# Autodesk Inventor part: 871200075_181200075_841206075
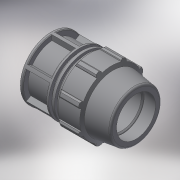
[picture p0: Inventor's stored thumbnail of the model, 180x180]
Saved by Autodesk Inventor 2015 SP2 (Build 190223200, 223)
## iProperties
Created: 2017-02
Part Number: 871200075_181200075_841206075
Material: Generic
Description: PLASSON END PLUG 75
Document SubType Name: Modeling
Designer: KIM
Mass: 947.017 g
Surface Area: 1382.98 cm^2
Volume: 947.017 cm^3
Density: 1 g/cm^3
Appearance: Default
Author: Кирилл
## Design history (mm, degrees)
derived "87120.ipt"
feature "Solid1::87120.ipt"
tag "TaggingFeature1"
body "Solid1"
other parameters: "d2" = 75, "d4" = 25.28571, "d5" = 44.25, "d7" = 132, "d8" = 99, "d9" = 25.28571, "d11" = 5.05714, "d12" = 105.6, "d13" = 120 deg, "d14" = 97.5, "d15" = 8 deg, "d16" = 118.8, "d18" = 3.75, "d19" = 35 deg, "d20" = 17.5 deg, "d21" = 122.76, "d23" = 0, "d25" = 360 deg, "d27" = 2.64, "d34" = 6.6, "d36" = 0, "d42" = 44.25, "d43" = 3.96, "d46" = 2.25, "d53" = 1.5, "d55" = 360 deg, "d59" = 44.25, "d64" = 177, "d66" = 17.16, "d67" = 10.56, "d68" = 161, "d70" = 20.22857, "d71" = 5.05714, "d72" = 116.424, "d75" = 10.11429, "d_" = 75, "E_" = 132, "H_" = 177, "l_" = 161
